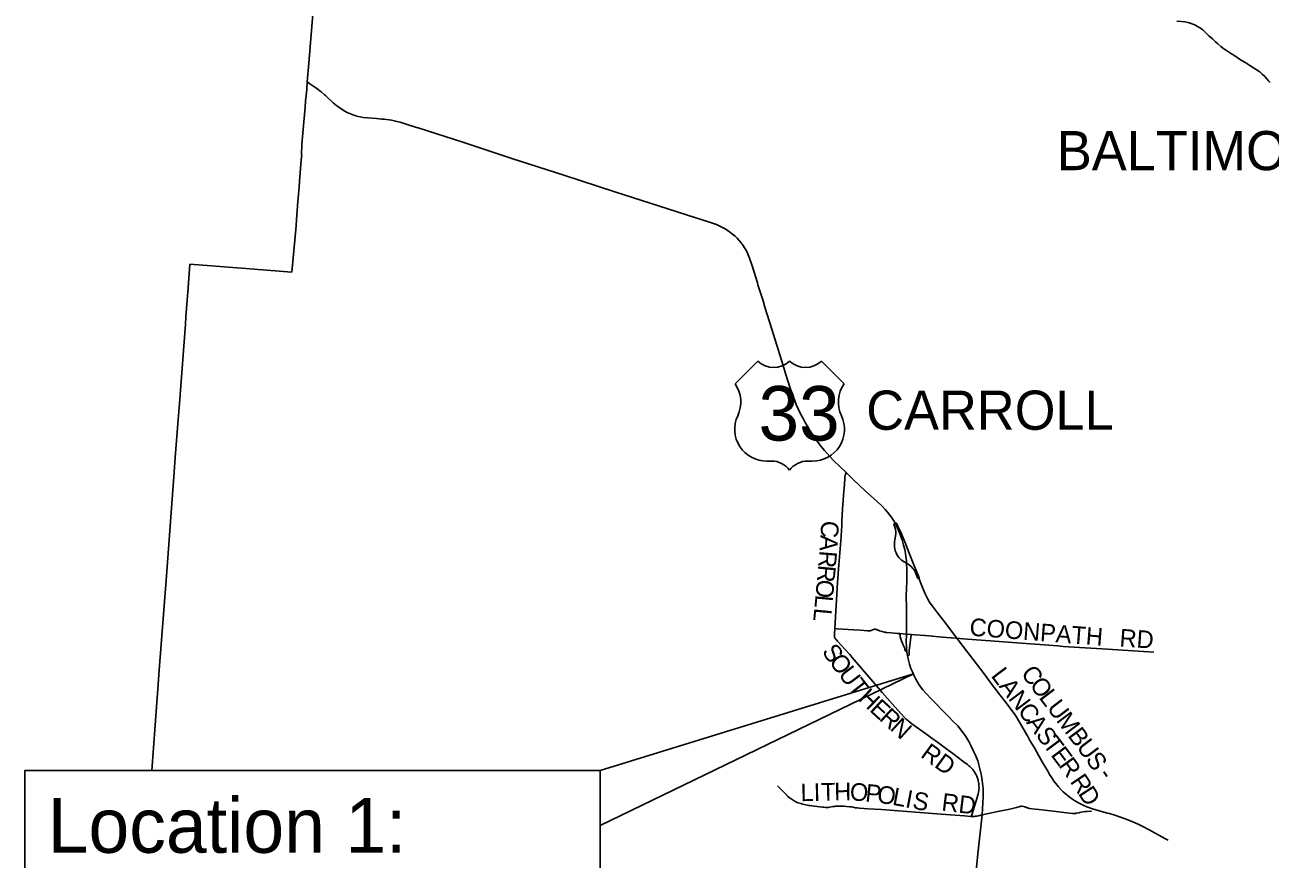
# Model space of a CAD drawing. Extents: x 1761803 to 2441803, y 509895 to 949895.
# Drawn here: x 1869764 to 1933337, y 729125 to 771732 of the extents above; entities that cross this region are included whole.
import ezdxf

# ---------------------------------------------------------------- set-up
doc = ezdxf.new("R2010")
doc.units = 0
for name, color, linetype in [('GM_X_County', 7, 'Continuous'), ('GM_X_County_Road', 7, 'Continuous'), ('GM_X_County_Road_Text', 7, 'Continuous'), ('GM_X_Minor_Lake', 7, 'Continuous'), ('GM_X_Minor_River_Text', 7, 'Continuous'), ('GM_X_State_Location', 7, 'Continuous'), ('GM_X_US_Location', 7, 'Continuous')]:
    doc.layers.add(name, color=color, linetype=linetype)

msp = doc.modelspace()

# ---------------------------------------------------------------- linework, layer by layer
at = {"layer": 'GM_X_County'}
msp.add_lwpolyline([(1884479, 772480), (1884260, 769783), (1884177, 768820), (1884153, 768436), (1884120, 768132), (1884093, 767829), (1884077, 767538), (1883910, 765644), (1883888, 765099), (1883896, 765058), (1883889, 764973), (1883877, 764831), (1883785, 763758), (1883760, 763427), (1883733, 763091), (1883700, 762709), (1883625, 761796), (1883609, 761477), (1883392, 759110), (1880829, 759311), (1878189, 759504), (1878096, 758311), (1877984, 756828), (1877958, 756450), (1877649, 752393), (1877591, 751580), (1877433, 749641), (1877380, 748888), (1876989, 743600), (1876603, 738550), (1876584, 738285), (1876240, 733657)], dxfattribs=at)
at = {"layer": 'GM_X_County_Road'}
for points in [[(1917671, 734119), (1917650, 734135), (1917134, 734514), (1916899, 734692), (1916360, 735094), (1916068, 735307), (1915572, 735655), (1915277, 735863), (1915171, 735941), (1915041, 736041), (1914761, 736270), (1914655, 736372), (1914183, 736897), (1913534, 737637), (1912948, 738323), (1911999, 739426), (1911880, 739568), (1911621, 739841), (1911254, 740261), (1911168, 740360), (1911137, 740399), (1911119, 740427), (1911105, 740458), (1911101, 740474), (1911093, 740523), (1911091, 740557), (1911093, 740606), (1911113, 740900), (1911256, 743258), (1911325, 744156), (1911438, 745579), (1911462, 745955), (1911467, 746101), (1911470, 746396), (1911484, 746658), (1911512, 747017), (1911545, 747441), (1911560, 747719), (1911569, 747898), (1911587, 748078), (1911624, 748536), (1911631, 748609), (1911646, 748746), (1911651, 748774), (1911685, 748876)], [(1920913, 735476), (1920774, 735717), (1920495, 736202), (1920368, 736405), (1920298, 736514), (1919856, 737106), (1919545, 737509), (1918996, 738237), (1918733, 738582), (1918341, 739099), (1918007, 739536), (1917671, 739977), (1917345, 740410), (1917075, 740770), (1916724, 741225), (1916413, 741636), (1916153, 741974), (1916034, 742137), (1915953, 742252), (1915859, 742403), (1915807, 742500), (1915758, 742599), (1915716, 742703), (1915521, 743170), (1915398, 743473)], [(1911113, 740900), (1911235, 740894), (1912084, 740840), (1912409, 740819), (1912608, 740806), (1912788, 740792), (1912866, 740788), (1912915, 740789), (1912957, 740798), (1912976, 740805), (1913057, 740842), (1913084, 740852), (1913106, 740858), (1913123, 740862), (1913139, 740864), (1913156, 740864), (1913179, 740863), (1913199, 740860), (1913220, 740856), (1913252, 740847), (1913298, 740830), (1913399, 740786), (1913466, 740762), (1913529, 740743), (1913644, 740718), (1913685, 740710), (1913723, 740705), (1913777, 740700), (1913968, 740684), (1914169, 740667)], [(1914169, 740667), (1914320, 740655), (1914431, 740646), (1914780, 740617)], [(1914780, 740617), (1915018, 740597), (1915221, 740581), (1915712, 740541), (1915732, 740539)], [(1915732, 740539), (1915912, 740524), (1916064, 740511), (1916105, 740508), (1916416, 740482), (1916436, 740483), (1916809, 740450), (1917300, 740411), (1917345, 740410)], [(1917345, 740410), (1917667, 740383), (1919729, 740218), (1921348, 740099), (1922506, 740015), (1922772, 739992), (1923606, 739932), (1924768, 739858), (1925570, 739812), (1927395, 739694)], [(1928132, 730090), (1927968, 730182), (1927158, 730617), (1926836, 730790), (1926602, 730908), (1926366, 731018), (1925997, 731168), (1925605, 731307), (1925504, 731343), (1925362, 731388), (1925140, 731451), (1925035, 731479), (1924498, 731627), (1924222, 731710), (1923986, 731798), (1923823, 731869), (1923696, 731929), (1923515, 732018), (1923349, 732117), (1923209, 732208), (1922899, 732455), (1922771, 732568), (1922668, 732667), (1922535, 732811), (1922390, 732985), (1922301, 733109), (1922223, 733218), (1922153, 733323), (1922077, 733450), (1921985, 733613), (1921706, 734094), (1921534, 734394), (1921302, 734804), (1921078, 735186), (1921010, 735315), (1920945, 735421), (1920913, 735476)], [(1918082, 731306), (1918102, 731386), (1918384, 732278), (1918438, 732467), (1918452, 732531), (1918470, 732661), (1918476, 732791), (1918475, 732857), (1918464, 732987), (1918441, 733116), (1918425, 733179), (1918384, 733303), (1918360, 733364), (1918333, 733424), (1918303, 733482), (1918236, 733594), (1918198, 733647), (1918157, 733699), (1918104, 733761), (1918012, 733853), (1917963, 733896), (1917886, 733958), (1917671, 734119)], [(1908182, 732862), (1908201, 732844), (1908334, 732715), (1908436, 732619), (1908494, 732563), (1908563, 732495), (1908611, 732441), (1908645, 732403)], [(1908645, 732403), (1908651, 732396), (1908722, 732316), (1908780, 732271), (1908835, 732238), (1908892, 732206), (1909043, 732104), (1909097, 732069), (1909191, 732023), (1909244, 732002), (1909305, 731983), (1909385, 731962), (1909487, 731938), (1909710, 731883), (1909775, 731870), (1909840, 731861), (1909938, 731850), (1910084, 731834), (1910492, 731781), (1910556, 731772), (1910638, 731764), (1910687, 731762), (1910737, 731763), (1910786, 731766), (1910851, 731775), (1911011, 731807), (1911092, 731818), (1911157, 731825), (1911222, 731828), (1911354, 731829), (1911468, 731828), (1911599, 731822), (1911714, 731814), (1911877, 731800), (1911974, 731788), (1912055, 731774), (1912167, 731751), (1912248, 731736), (1912378, 731720), (1912820, 731700), (1913490, 731655), (1916545, 731426), (1917742, 731329), (1918053, 731306), (1918082, 731306), (1918136, 731304), (1918201, 731305), (1918251, 731309), (1918300, 731315), (1918364, 731327), (1918447, 731344), (1918634, 731383), (1918878, 731436), (1919439, 731554), (1920049, 731680), (1920382, 731766), (1920509, 731801), (1920562, 731813), (1920593, 731819), (1920624, 731823), (1920653, 731825), (1920683, 731825), (1920747, 731817), (1920797, 731803), (1920830, 731791), (1920904, 731760)], [(1920904, 731760), (1920943, 731744), (1920975, 731732), (1921002, 731725), (1921056, 731714), (1921340, 731679), (1921536, 731658), (1921813, 731625), (1922118, 731590), (1922410, 731553), (1922937, 731497), (1923247, 731460), (1923329, 731453), (1923362, 731453), (1923395, 731458), (1923443, 731469), (1923465, 731473), (1923572, 731493), (1923615, 731502), (1923685, 731516), (1923797, 731536), (1923895, 731549), (1923976, 731557), (1924193, 731574), (1924217, 731575)]]:
    msp.add_lwpolyline(points, dxfattribs=at)
at = {"layer": 'GM_X_County_Road_Text'}
for p, q in [((1907180, 754561), (1906020, 753401)), ((1911589, 753401), (1910429, 754561)), ((1907644, 749457), (1907877, 749457)), ((1909733, 749457), (1909965, 749457))]:
    msp.add_line(p, q, dxfattribs=at)
for centre, radius, start, end in [((1907993, 755390), 1160, 225.573, 314.427), ((1909617, 755390), 1160, 225.573, 314.427), ((1904690, 752470), 1624, 334.54712, 35.00093), ((1912919, 752470), 1624, 144.99907, 205.45288), ((1907626, 751081), 1624, 154.83192, 270.63826), ((1909983, 751081), 1624, 269.36174, 25.16808), ((1907877, 748297), 1160, 36.8699, 90), ((1909733, 748297), 1160, 90, 143.1301)]:
    msp.add_arc(centre, radius, start, end, dxfattribs=at)
at = {"layer": 'GM_X_Minor_Lake'}
for points in [[(1928580, 771922), (1928822, 771907), (1928978, 771889), (1929138, 771858), (1929210, 771840), (1929303, 771809), (1929386, 771777), (1929489, 771739), (1929638, 771652), (1929779, 771559), (1929802, 771542)], [(1929802, 771542), (1929899, 771474), (1930037, 771351), (1930216, 771179), (1930390, 771012), (1930548, 770869), (1930664, 770765), (1930823, 770637), (1930983, 770515), (1931166, 770390), (1931363, 770262), (1931493, 770181), (1931654, 770075), (1931833, 769955), (1932099, 769790), (1932304, 769662), (1932489, 769542), (1932628, 769455), (1932808, 769327), (1932940, 769223), (1933060, 769096), (1933176, 768975), (1933259, 768870), (1933337, 768785)]]:
    msp.add_lwpolyline(points, dxfattribs=at)
at = {"layer": 'GM_X_Minor_River_Text'}
for points in [[(1884177, 768820), (1884313, 768722), (1884408, 768658), (1884662, 768482), (1884890, 768312), (1885062, 768163), (1885108, 768123)], [(1885108, 768123), (1885143, 768093), (1885527, 767732), (1885689, 767594), (1885838, 767488), (1886063, 767339), (1886219, 767253), (1886386, 767185), (1886563, 767121), (1886676, 767086)], [(1886676, 767086), (1886702, 767078), (1886878, 767038), (1887032, 767010), (1887260, 766982), (1887494, 766969), (1887723, 766948), (1887986, 766924), (1888113, 766912), (1888478, 766864), (1888688, 766822), (1888913, 766767), (1888972, 766749), (1889078, 766717), (1889439, 766595), (1889820, 766475), (1889843, 766468)], [(1889843, 766468), (1890800, 766162), (1892071, 765755), (1894624, 764915), (1897287, 764057), (1899884, 763208), (1902593, 762334), (1903587, 762014), (1904669, 761666), (1905065, 761533), (1905177, 761484), (1905319, 761419), (1905474, 761335), (1905626, 761242), (1905733, 761167), (1905887, 761050), (1906026, 760937), (1906120, 760839), (1906234, 760715), (1906331, 760597), (1906431, 760463), (1906506, 760347), (1906597, 760193), (1906657, 760066), (1906751, 759825), (1906889, 759428), (1907159, 758563), (1907182, 758463), (1907450, 757646), (1907545, 757322), (1907899, 756190), (1908221, 755157), (1908478, 754331), (1908599, 753924), (1908840, 753174), (1908895, 752997), (1908972, 752781), (1909065, 752546), (1909149, 752340), (1909367, 751872), (1909512, 751592), (1909624, 751385), (1909762, 751149), (1909845, 751011), (1909898, 750924), (1909911, 750906)], [(1909911, 750906), (1909989, 750789), (1910113, 750603), (1910405, 750213), (1910591, 749989), (1910858, 749688), (1911057, 749462), (1911358, 749188), (1911685, 748876)], [(1911685, 748876), (1911797, 748765)], [(1911797, 748765), (1912049, 748514), (1912670, 747936), (1913290, 747375), (1913533, 747149), (1913688, 746986), (1913809, 746850), (1913925, 746700), (1913994, 746610), (1914065, 746510), (1914135, 746404), (1914214, 746272)], [(1914214, 746272), (1914214, 746272), (1914410, 745783), (1914549, 745429), (1914629, 745161), (1914688, 744934), (1914725, 744741), (1914741, 744580), (1914776, 744360), (1914778, 744243), (1914794, 743900), (1914783, 743318), (1914763, 742566), (1914776, 741949), (1914780, 740617), (1914765, 740190), (1914771, 740020), (1914778, 739863), (1914791, 739754), (1914798, 739689), (1914823, 739528), (1914861, 739347), (1914894, 739210), (1914932, 739074), (1915001, 738865), (1915075, 738689), (1915145, 738523), (1915230, 738351), (1915321, 738196), (1915441, 737995), (1915615, 737777), (1915772, 737587), (1916025, 737312), (1916335, 737002), (1916585, 736755), (1916956, 736377), (1917130, 736184), (1917396, 735932), (1917561, 735718), (1917806, 735384), (1917952, 735131), (1918078, 734898), (1918201, 734637), (1918297, 734426), (1918412, 734139), (1918507, 733809), (1918588, 733464), (1918627, 733264), (1918660, 733000), (1918682, 732710), (1918689, 732527), (1918691, 732303), (1918634, 731383), (1918432, 729548), (1918276, 728038)]]:
    msp.add_lwpolyline(points, dxfattribs=at)
at = {"layer": 'GM_X_State_Location'}
for points in [[(1915136, 738590), (1899141, 733657), (1899141, 730845)], [(1869764, 718823), (1899141, 718823), (1899141, 733657), (1869764, 733657)]]:
    msp.add_lwpolyline(points, close=True, dxfattribs=at)
at = {"layer": 'GM_X_US_Location'}
for points in [[(1914214, 746272), (1914125, 746236), (1914176, 746085), (1914207, 745957), (1914222, 745857), (1914222, 745730), (1914205, 745612), (1914179, 745428), (1914166, 745325), (1914153, 745202), (1914156, 745144), (1914156, 745077), (1914174, 744949), (1914194, 744877), (1914240, 744760), (1914297, 744655), (1914379, 744534), (1914524, 744399), (1914657, 744309), (1914778, 744243), (1914916, 744148), (1915016, 744064), (1915103, 743974), (1915144, 743915), (1915195, 743846), (1915236, 743757), (1915290, 743631), (1915341, 743498), (1915361, 743457), (1915398, 743473)], [(1915398, 743473), (1915423, 743483), (1915307, 743778), (1915156, 744152), (1915018, 744499), (1914916, 744755), (1914831, 744976), (1914746, 745196), (1914693, 745326), (1914472, 745850), (1914352, 746103), (1914257, 746290), (1914214, 746272)], [(1914431, 740646), (1914432, 740618), (1914442, 740558), (1914454, 740478), (1914476, 740363), (1914546, 740191), (1914639, 739985), (1914664, 739916), (1914693, 739840), (1914724, 739741), (1914791, 739754)], [(1914823, 739528), (1914905, 739547), (1914905, 739688), (1914914, 739808), (1914925, 739898), (1915017, 740573), (1915018, 740597)]]:
    msp.add_lwpolyline(points, dxfattribs=at)

# ---------------------------------------------------------------- texts
at = {"layer": 'GM_X_County_Road'}
for s, height, rotation, p in [('BALTIMORE', 2000, 0.00001, (1922450, 764311)), ('CARROLL', 2000, 0.00001, (1912719, 751054)), ('C', 900, 266.52553, (1910432, 746426)), ('A', 900, 266.26806, (1910387, 745689)), ('R', 900, 265.37029, (1910336, 744902)), ('R', 900, 264.73399, (1910276, 744168)), ('O', 900, 264.69129, (1910209, 743432)), ('L', 900, 264.69069, (1910135, 742644)), ('L', 900, 264.69069, (1910073, 741973)), ('COONPATH', 900, 355.60163, (1917969, 740543)), ('RD', 900, 356.05514, (1925630, 739992)), ('S', 900, 305.15346, (1910423, 739721)), ('O', 900, 306.51226, (1910786, 739206)), ('U', 900, 306.90505, (1911261, 738564)), ('L', 900, 307.03189, (1919055, 738488)), ('C', 900, 307.02914, (1920579, 738600)), ('T', 900, 307.85725, (1911747, 737917)), ('A', 900, 307.03131, (1919460, 737951)), ('O', 900, 307.028, (1921024, 738010)), ('H', 900, 316.26674, (1912256, 737279)), ('N', 900, 307.0331, (1919937, 737318)), ('L', 900, 307.02847, (1921501, 737377)), ('E', 900, 317.39646, (1912843, 736718)), ('R', 900, 317.39886, (1913338, 736262)), ('C', 900, 307.03149, (1920414, 736686)), ('U', 900, 307.028, (1921907, 736840)), ('N', 900, 317.67448, (1913886, 735759)), ('A', 900, 307.03131, (1920860, 736096)), ('M', 900, 307.03076, (1922384, 736208)), ('S', 900, 307.03146, (1921337, 735464)), ('B', 900, 307.02602, (1922972, 735428)), ('RD', 900, 324.1181, (1915443, 734373)), ('T', 900, 307.03189, (1921702, 734979)), ('E', 900, 306.86047, (1922107, 734442)), ('U', 900, 307.0178, (1923417, 734838)), ('R', 900, 305.79811, (1922509, 733907)), ('S', 900, 304.58096, (1923888, 734213)), ('I', 900, 1.37495, (1910048, 732096)), ('T', 900, 1.37942, (1910418, 732105)), ('H', 900, 0.72198, (1911088, 732121)), ('O', 900, 356.05441, (1911860, 732132)), ('R', 900, 303.99534, (1923096, 733087)), ('-', 900, 303.68791, (1924528, 733440)), ('L', 900, 1.38226, (1909375, 732080)), ('P', 900, 353.66824, (1912641, 732078)), ('O', 900, 352.10959, (1913238, 732012)), ('L', 900, 349.52062, (1914012, 731905)), ('I', 900, 349.22169, (1914672, 731783)), ('S', 900, 349.32106, (1915037, 731713)), ('RD', 900, 353.11772, (1916533, 731609)), ('D', 900, 303.06266, (1923507, 732477))]:
    msp.add_text(s, height=height, rotation=rotation, dxfattribs=at).set_placement(p)
at = {"layer": 'GM_X_County_Road_Text'}
msp.add_text('33', height=2784.4, dxfattribs=at).set_placement((1907220, 750501))
at = {"layer": 'GM_X_State_Location'}
msp.add_text('Location 1:', height=2800, dxfattribs=at).set_placement((1870927, 729447))

doc.saveas('drawing.dxf')
